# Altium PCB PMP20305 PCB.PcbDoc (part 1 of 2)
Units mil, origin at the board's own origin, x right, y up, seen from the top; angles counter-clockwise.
Board outline 4400 x 7000 mil, 4 copper layers (Top Layer, GND, Signal Layer 2, Bottom Layer), stack 61.2 mil thick; 121 components, 72 nets, 974 pads, 10 vias.
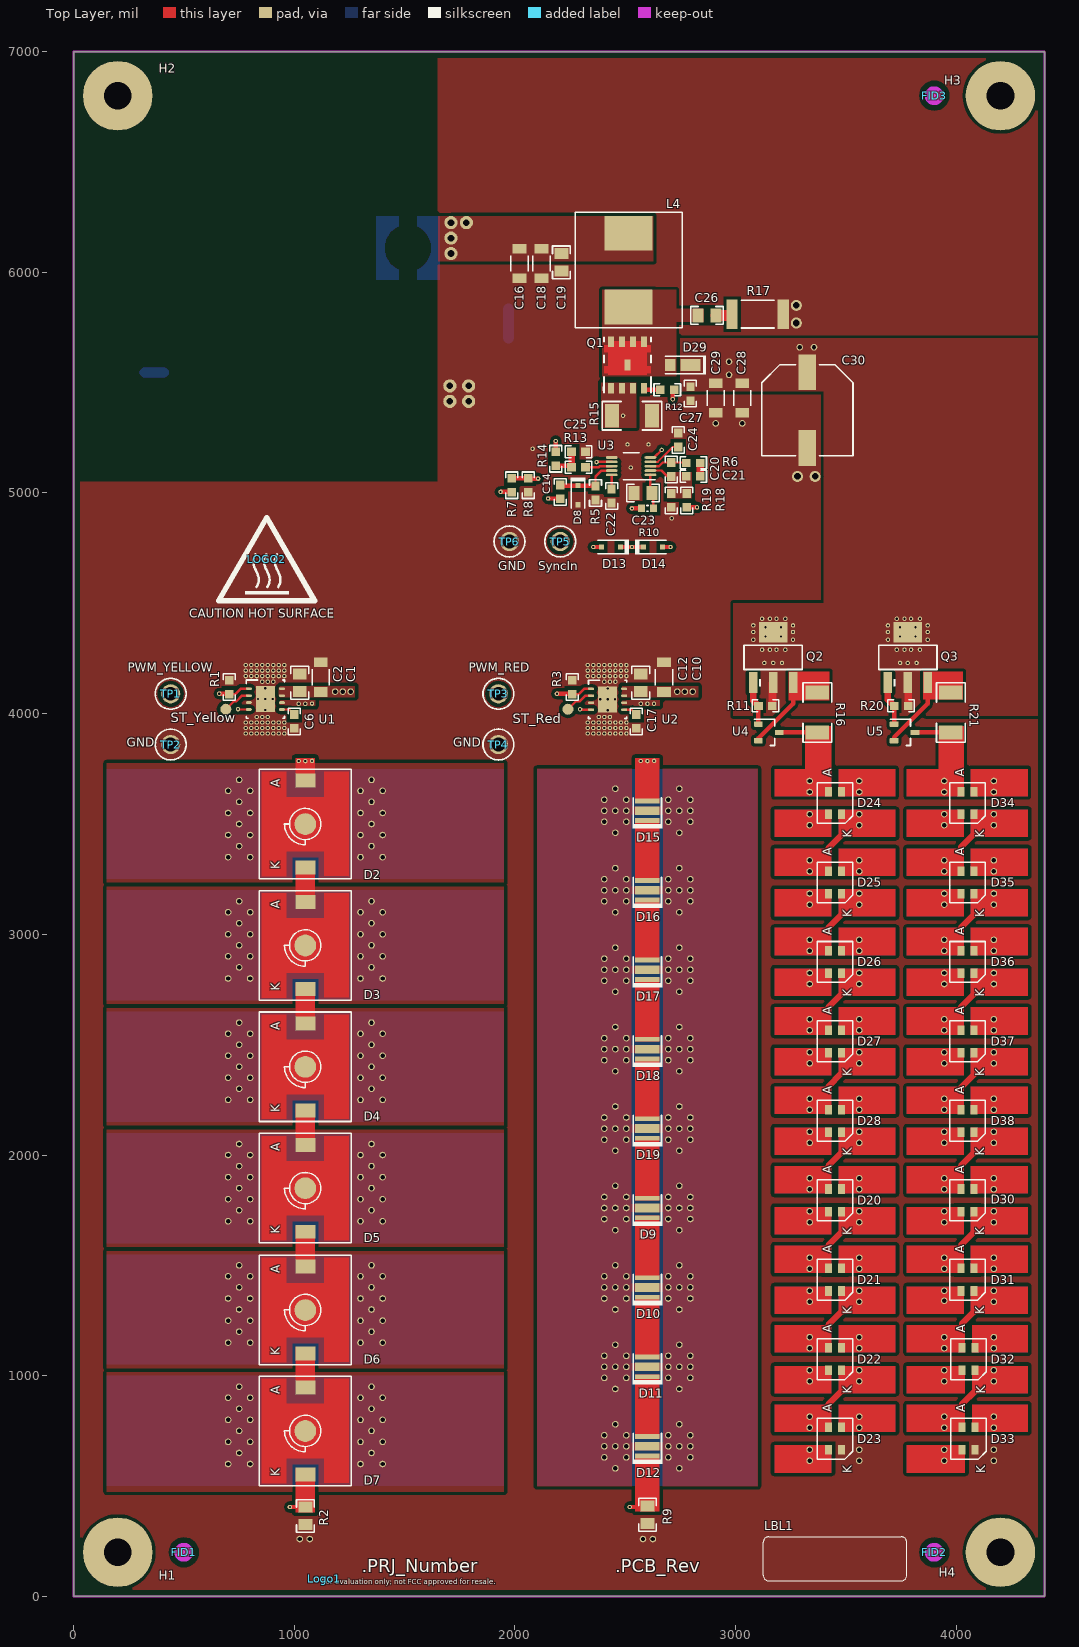
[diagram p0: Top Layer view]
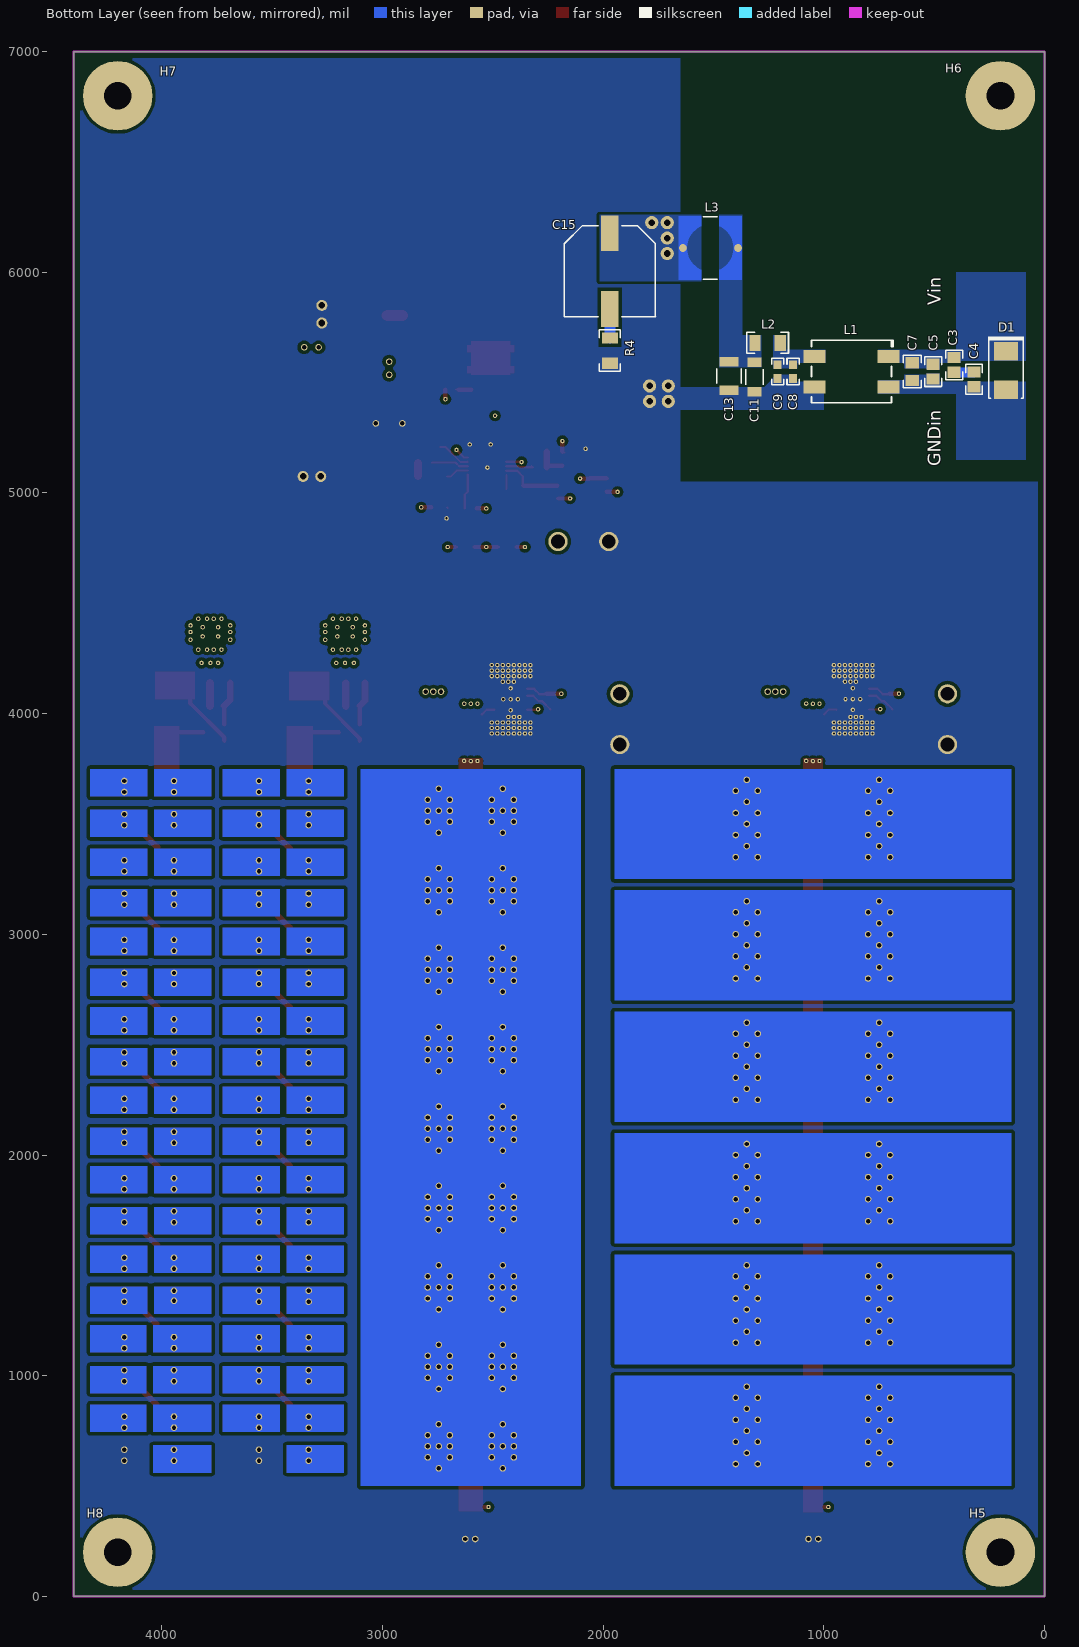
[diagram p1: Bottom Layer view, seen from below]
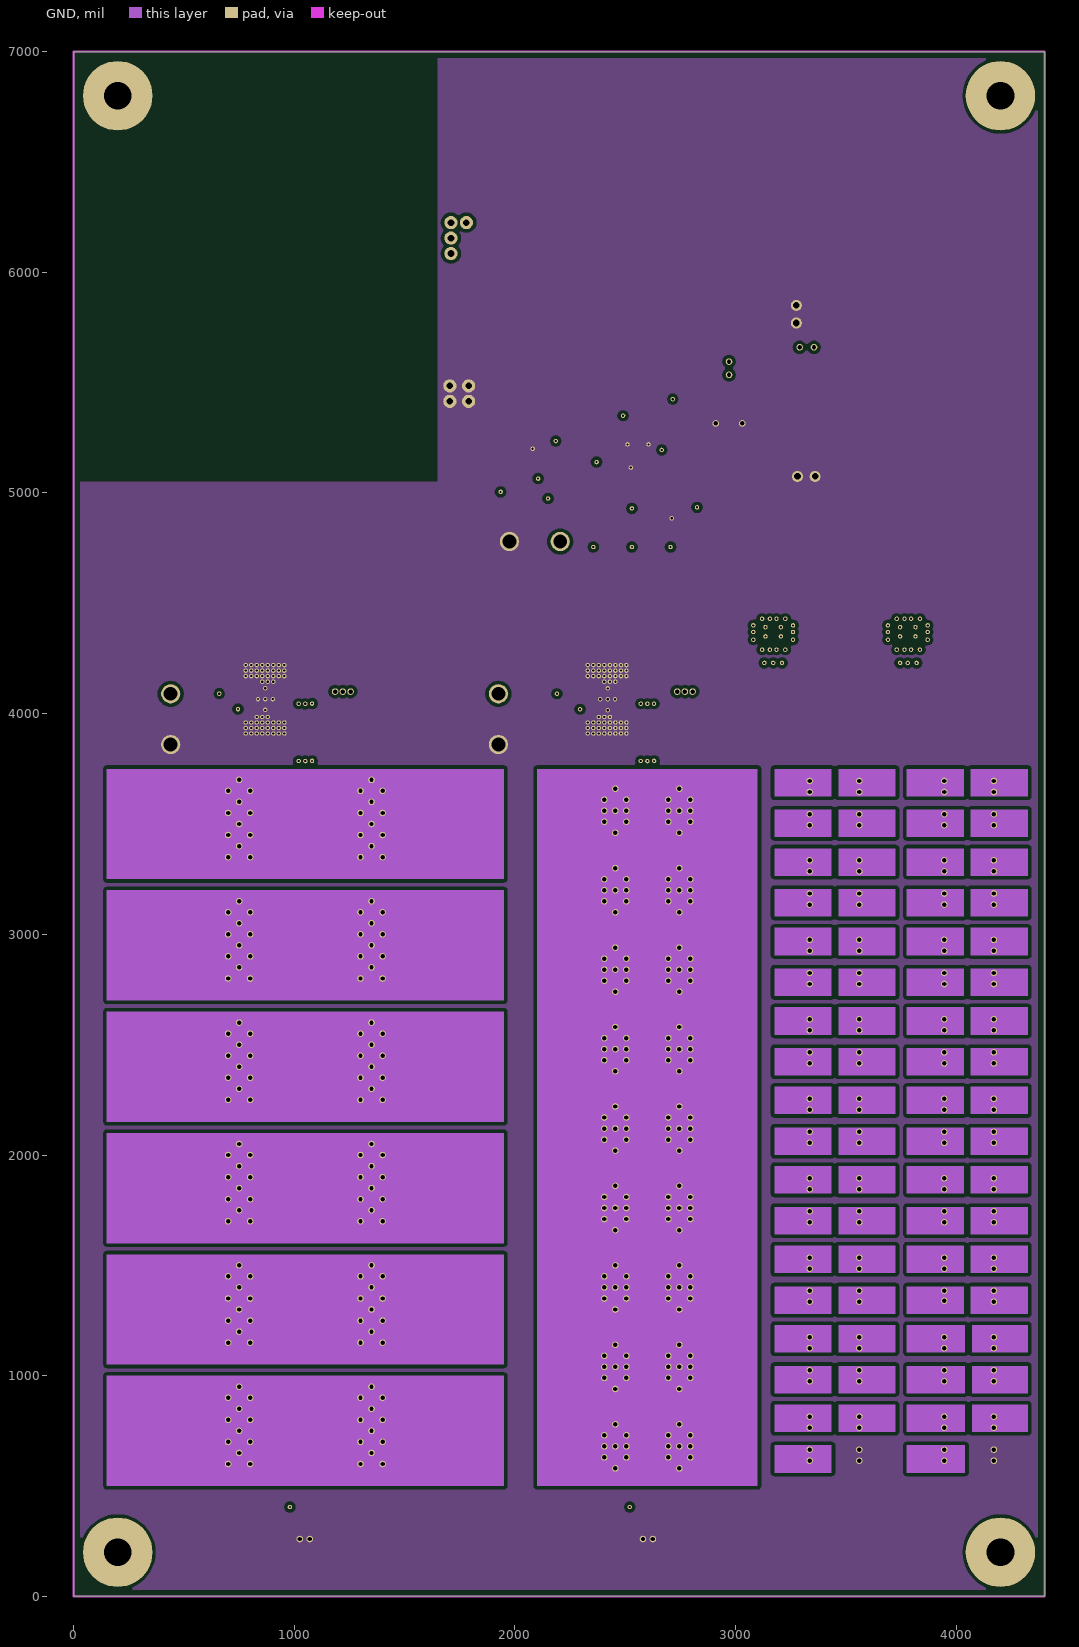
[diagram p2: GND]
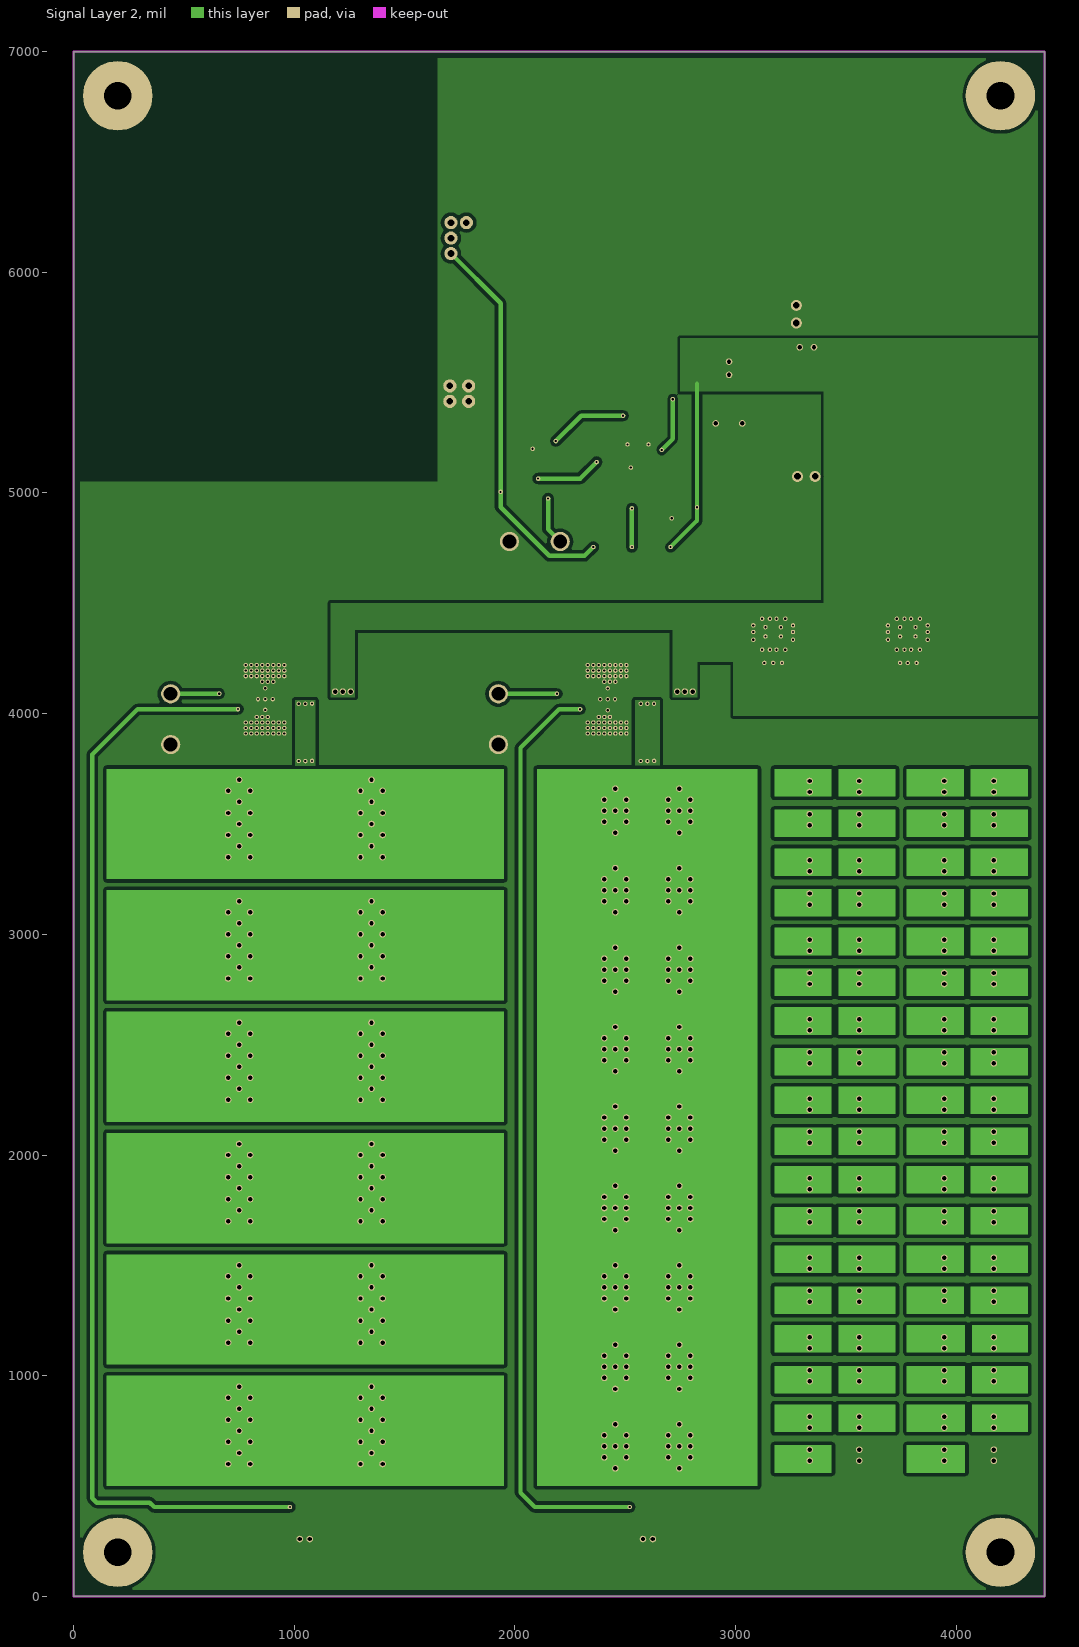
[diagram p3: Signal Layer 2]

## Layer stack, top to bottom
Top Solder: solder mask 0.4, Solder Resist, Dk 3.5
Top Layer: signal copper 2.8
Dielectric1: core 12, FR-4, Dk 4.2
GND: signal copper 2.8
Dielectric 3: prepreg 26, FR-4, Dk 4.2
Signal Layer 2: signal copper 2.8
Dielectric 2: core 12, FR-4, Dk 4.2
Bottom Layer: signal copper 2.8
Bottom Solder: solder mask 0.4, Solder Resist, Dk 3.5

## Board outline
0,0 4400,0 4400,7000 0,7000

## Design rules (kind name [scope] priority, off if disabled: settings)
AcuteAngle [All] p1: minimum=4.50000000000000E+0001 checktracksonly=FALSE
AssemblyTestPointUsage [All] p1: valid=2
Clearance Clearance_Keepouts [((IsTrack Or IsArc) And Not InPoly) And IsFree and IsKeepOut vs ((IsTrack Or IsArc) And Not InPoly) And IsFree and IsKeepOut] p1: gap=0 ignorepadtopadclearanceinfootprint=FALSE
Clearance Clearance_BoardEdge_MountingHoles [OnCopper and InComponentClass('Mounting Holes') vs IsKeepOut] p2: gap=35 ignorepadtopadclearanceinfootprint=FALSE except(0: Arc-Hole Track-Hole SMDPad-Hole THPad-Hole Via-Hole Fill-Hole Poly-Hole Region-Hole Text-Hole)
Clearance Clearance_BoardEdge_Poly [OnCopper and InPoly vs IsKeepOut] p3: gap=25 ignorepadtopadclearanceinfootprint=FALSE except(0: Arc-Hole Track-Hole SMDPad-Hole THPad-Hole Via-Hole Fill-Hole Poly-Hole Region-Hole Text-Hole)
Clearance Clearance_BoardEdge [OnCopper and Not InComponentClass('Logo') and not InComponentClass('FiducialMark') and not InRegion(1000,500,4000,800) and Not IsKeepout vs IsKeepOut] p4: gap=45 ignorepadtopadclearanceinfootprint=FALSE except(0: Arc-Hole Track-Hole SMDPad-Hole THPad-Hole Via-Hole Fill-Hole Poly-Hole Region-Hole Text-Hole)
Clearance Clearance_Poly [InPolygon] p5: gap=15 ignorepadtopadclearanceinfootprint=FALSE except(0: Arc-Hole Track-Hole SMDPad-Hole THPad-Hole Via-Hole Fill-Hole Poly-Hole Region-Hole Text-Hole)
Clearance [All] p6: gap=7.87 ignorepadtopadclearanceinfootprint=FALSE except(0: Arc-Hole Track-Hole SMDPad-Hole THPad-Hole Via-Hole Fill-Hole Poly-Hole Region-Hole Text-Hole)
ComponentClearance ComponentClearance_MountingHoles_FiducialMarks [InComponentClass('Mounting Holes') vs InComponentClass('FiducialMark')] p1: gap=50 collisioncheckmode=3 verticalgap=10 showdistances=FALSE
ComponentClearance ComponentClearance_Shunt [InComponentClass('Header') vs InComponentClass('Shunt')] p2: gap=0 collisioncheckmode=3 verticalgap=0 showdistances=FALSE
ComponentClearance ComponentClearance_Logo [InComponentClass('Logo')] p3: gap=50 collisioncheckmode=3 verticalgap=10 showdistances=FALSE
ComponentClearance ComponentClearance_ScrewToNut [(HasFootprint('NY PMS 440 0025 PH')) vs (HasFootprint('Keystone_1902C'))] p4: gap=5 collisioncheckmode=3 verticalgap=10 showdistances=FALSE
ComponentClearance ComponentClearance_MountingHoles [InComponentClass('Mounting Holes')] p5: gap=150 collisioncheckmode=3 verticalgap=100000 showdistances=FALSE
ComponentClearance ComponentClearance_SmallPassives [HasFootprint('0201*') or HasFootprint('0402*') or HasFootprint('0508') or HasFootprint('0603*') or HasFootprint('0612') or HasFootprint('0805*') or HasFootprint('0815*') or HasFootprint('0830*') or HasFootprint('1206*') or HasFootprint('1210*') or HasFootprint('1808*') or HasFootprint('1812*') or HasFootprint('1825*') or HasFootprint('2010*') or HasFootprint('2220*') or HasFootprint('2225*') or HasFootprint('2512*') or HasFootprint('2728*') or HasFootprint('3518*') vs HasFootprint('0201*') or HasFootprint('0402*') or HasFootprint('0508') or HasFootprint('0603*') or HasFootprint('0612') or HasFootprint('0805*') or HasFootprint('0815*') or HasFootprint('0830*') or HasFootprint('1206*') or HasFootprint('1210*') or HasFootprint('1808*') or HasFootprint('1812*') or HasFootprint('1825*') or HasFootprint('2010*') or HasFootprint('2220*') or HasFootprint('2225*') or HasFootprint('2512*') or HasFootprint('2728*') or HasFootprint('3518*')] p6: gap=20 collisioncheckmode=3 verticalgap=10 showdistances=FALSE
ComponentClearance ComponentClearance_THtoSMT [IsThruComponent vs IsSMTComponent] p7: gap=50 collisioncheckmode=3 verticalgap=30 showdistances=FALSE
ComponentClearance ComponentClearance_THtoTH [IsThruComponent vs IsThruComponent] p8: gap=100 collisioncheckmode=3 verticalgap=30 showdistances=FALSE
ComponentClearance [All] p9: gap=30 collisioncheckmode=3 verticalgap=10 showdistances=FALSE
DiffPairsRouting [All] p1: maxlimit=100 minlimit=10 mostfreqgap=10 toplayer_minwidth=15 toplayer_maxwidth=15 toplayer_prefwidth=15 midlayer1_minwidth=15 midlayer1_maxwidth=15 midlayer1_prefwidth=15 midlayer2_minwidth=15 midlayer2_maxwidth=15 midlayer2_prefwidth=15 bottomlayer_minwidth=15 bottomlayer_maxwidth=15 bottomlayer_prefwidth=15 maxuncoupledlength=1000
FabricationTestPointUsage TestPointUsage [All] p1: valid=2 allowmultiple=FALSE
FabricationTestpoint Testpoint [All] p1: side=3 testpointundercomponent=TRUE minsize=40 maxsize=100 preferedsize=60 minholesize=0 maxholesize=40 preferedholesize=32 testpointgrid=1 allowsidetop=TRUE allowsidebottom=TRUE usegrid=TRUE gridtolerance=0.01
FanoutControl Fanout_LCC [IsLCC] p1: bgadir=Out bgaviamode=Centered fanoutstyle=Auto fanoutdirection=Alternating viagrid=1 // Fanout_LCC (Default Rule)
FanoutControl Fanout_BGA [IsBGA] p2: bgadir=Out bgaviamode=Centered fanoutstyle=Auto fanoutdirection=Alternating viagrid=1 // Fanout_BGA (Default Rule)
FanoutControl Fanout_Default [All] p4: bgadir=Out bgaviamode=Centered fanoutstyle=Auto fanoutdirection=Alternating viagrid=1 // Fanout_Default (Default Rule)
FanoutControl Fanout_Small [(CompPinCount < 5)] p5: bgadir=Out bgaviamode=Centered fanoutstyle=Auto fanoutdirection=OutThenIn viagrid=1 // Fanout_Small (Default Rule)
HoleSize [All] p1: absolutevalues=TRUE maxlimit=251 minlimit=8 maxpercent=80.000 minpercent=20.000
MinimumAnnularRing MinimumAnnularRing_ThermalPadVias [IsVia and InAnyComponent] p1: minimumring=5
MinimumAnnularRing [All] p2: minimumring=5
MinimumSolderMaskSliver MinimumSolderMaskSliver_Logo [InComponentClass('Logo') vs InComponentClass('Logo')] p1: minsoldermaskwidth=0.7
MinimumSolderMaskSliver [All] p2: minsoldermaskwidth=3.94
PlaneConnect [All] p1: planeconnectstyle=Direct reliefexpansion=10 reliefentries=4 reliefconductorwidth=10 reliefairgap=10
PolygonConnect [All] p1: connectstyle=Direct reliefconductorwidth=10 reliefentries=4 polygonreliefangle="90 Angle" airgapwidth=10
RoutingVias ThermalPadVias [IsVia and InAnyComponent] p1: holewidth=7.87 width=19.68 viastyle="Through Hole" minholewidth=7.87 minwidth=19.68 maxholewidth=12.99 maxwidth=23.62
RoutingVias [All] p2: holewidth=16 width=34 viastyle="Through Hole" minholewidth=7.87 minwidth=26 maxholewidth=40 maxwidth=65
SilkToBoardRegionClearance [Not ((IsComment or IsDesignator) And (Hide <> 'False')) and not InRegion(1000,500,4000,800)] p1:
SilkToSilkClearance SilkToSilkClearance_Pb-FreeLogo [(HasFootprint('Pb-Free_Overlay_Medium') OR HasFootprint('Pb-Free_Overlay_Small')) vs (HasFootprint('Pb-Free_Overlay_Medium') OR HasFootprint('Pb-Free_Overlay_Small'))] p1: silktosilkclearance=0
SilkToSilkClearance [All] p2: silktosilkclearance=4
SilkToSolderMaskClearance SilkToComonentPadClearance [IsPad and InAnycomponent] p1: minsilkscreentomaskgap=5 clearancetoexposedcopper=TRUE
SilkToSolderMaskClearance "Silk to Solder Mask Opening" [All] p2: minsilkscreentomaskgap=4 clearancetoexposedcopper=FALSE
SolderMaskExpansion [All] p1: expansion=1.97
Width [All] p1: maxlimit=100 minlimit=6 preferedwidth=10 checkconnectedcopper=TRUE
15 further rules are at their usual default settings.

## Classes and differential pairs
component class FiducialMark: FID1 FID2 FID3
component class PMP20305_EVM_Hardware: FID1 FID2 FID3 H1 H2 H3 H4 H5 H6 H7 H8 LBL1 Logo1 LOGO2
component class "PMP20305 Schematic": C1 C2 C3 C4 C5 C6 C7 C8 C9 C10 C11 C12 C13 C14 C15 C16 C17 C18 C19 C20 C21 C22 C23 C24 C25 C26 C27 C28 C29 C30 D1 D2 D3 D4 D5 D6 D7 D8 D9 D10 D11 D12 D13 D14 D15 D16 D17 D18 D19 D20 D21 D22 D23 D24 D25 D26 D27 D28 D29 D30 D31 D32 D33 D34 D35 D36 D37 D38 L1 L2 L3 L4 Q1 Q2 Q3 R1 R2 R3 R4 R5 R6 R7 R8 R9 R10 R11 R12 R13 R14 R15 R16 R17 R18 R19 R20 R21 TP1 TP2 TP3 TP4 TP5 TP6 U1 U2 U3 U4 U5
component class Label: LBL1
component class "Mounting Holes": H1 H2 H3 H4

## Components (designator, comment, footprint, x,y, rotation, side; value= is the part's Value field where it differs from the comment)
C1 "GRM31CR71H475KA12L" 1206_180 1120,4165 r90 top
C2 "08055C104JAT2A" 0805_HV 1025,4140 r90 top
C3 "CGA4J3X7S2A105K125AB" 0805 410,5580 r270 bottom
C4 "CGA4J3X7S2A105K125AB" 0805 320,5515 r270 bottom
C5 "CGA4J3X7S2A105K125AB" 0805 505,5550 r270 bottom
C6 "GRM188R71C473KA01D" 0603 1000,3965 r270 top
C7 "CGA4J2X7R2A104K125AA" 0805_HV 600,5550 r270 bottom
C8 "GRM188R71H104KA93D" 0603 1140,5550 r90 bottom
C9 "UMK107AB7105KA-T" 0603 1210,5550 r270 bottom
C10 "GRM31CR71H475KA12L" 1206_180 2675,4165 r90 top
C11 "GRM31CR71H475KA12L" 1206_180 1315,5525 r270 bottom
C12 "08055C104JAT2A" 0805_HV 2570,4140 r90 top
C13 "C3225X7R1H106M250AC" 1210_280 1430,5530 r270 bottom
C14 "06035A101JAT2A" 0603 2205,5005 r90 top
C15 "EEE-FC1H470P" SM_RADIAL_G 1970,6005 r270 bottom
C16 "GRM31CR71H475KA12L" 1206_180 2020,6040 r270 top
C17 "GRM188R71C473KA01D" 0603 2550,3965 r270 top
C18 "GRM31CR71H475KA12L" 1206_180 2120,6040 r270 top
C19 "C2012X7R1H225K125AC" 0805_HV 2210,6045 r270 top
C20 "GRM188R71C184KA01D" 0603 2707.98,5106.28 r90 top
C21 "GRM1885C1E561JA01D" 0603 2807.98,5076.28 r0 top
C22 "GCM155R71C224KE02" 0603 2437.98,4986.28 r270 top
C23 "08055C104JAT2A" 0805_HV 2580,5000 r180 top
C24 "885012206071" 0603 2740,5240 r270 top
C25 "06035A101JAT2A" 0603 2287.98,5186.28 r0 top
C26 "C0805C331J1GACTU" 0805_HV 2870,5805 r180 top
C27 "CGA3E3X8R1H104K080AB" 0603 2795,5450 r270 top
C28 "C3216X7R1H475M160AC" 1206_190 3030,5430 r270 top
C29 "C3216X7R1H475M160AC" 1206_190 2910,5430 r270 top
C30 "EEE-FC1V221P" SM_RADIAL_G 3325,5375 r270 top
D1 "SMBJ18A-13-F" SMB 175,5555 r270 bottom
D2 "LY-W5SM" LED_goldendragon 1050,3500 r90 top
D3 "LY-W5SM" LED_goldendragon 1050,2950 r90 top
D4 "LY-W5SM" LED_goldendragon 1050,2400 r90 top
D5 "LY-W5SM" LED_goldendragon 1050,1850 r90 top
D6 "LY-W5SM" LED_goldendragon 1050,1298 r90 top
D7 "LY-W5SM" LED_goldendragon 1050,750 r90 top
D8 "BAT42WS-7-F" SOD-323 2285,4990 r270 top
D9 "LH CP7P-2T3T-1" "LH CP7P_RED" 2600,1760 r0 top
D10 "LH CP7P-2T3T-1" "LH CP7P_RED" 2600,1400 r0 top
D11 "LH CP7P-2T3T-1" "LH CP7P_RED" 2600,1040 r0 top
D12 "LH CP7P-2T3T-1" "LH CP7P_RED" 2600,680 r0 top
D13 "BAV116WSQ-7" SOD-323 2435,4755 r180 top
D14 "BAV116WSQ-7" SOD-323 2625,4755 r0 top
D15 "LH CP7P-2T3T-1" "LH CP7P_RED" 2600,3560 r0 top
D16 "LH CP7P-2T3T-1" "LH CP7P_RED" 2600,3200 r0 top
D17 "LH CP7P-2T3T-1" "LH CP7P_RED" 2600,2840 r0 top
D18 "LH CP7P-2T3T-1" "LH CP7P_RED" 2600,2480 r0 top
D19 "LH CP7P-2T3T-1" "LH CP7P_RED" 2600,2120 r0 top
D20 "LR-E6SF" LED_PowerTOPLED_GF 3450,1795 r90 top
D21 "LR-E6SF" LED_PowerTOPLED_GF 3450,1435 r90 top
D22 "LR-E6SF" LED_PowerTOPLED_GF 3450,1075 r90 top
D23 "LR-E6SF" LED_PowerTOPLED_GF 3450,715 r90 top
D24 "LR-E6SF" LED_PowerTOPLED_GF 3450,3595 r90 top
D25 "LR-E6SF" LED_PowerTOPLED_GF 3450,3235 r90 top
D26 "LR-E6SF" LED_PowerTOPLED_GF 3450,2875 r90 top
D27 "LR-E6SF" LED_PowerTOPLED_GF 3450,2515 r90 top
D28 "LR-E6SF" LED_PowerTOPLED_GF 3450,2155 r90 top
D29 "FSV340FP" SOD-123HE 2760,5580 r180 top
D30 "LR-E6SF" LED_PowerTOPLED_GF 4050,1795 r90 top
D31 "LR-E6SF" LED_PowerTOPLED_GF 4050,1435 r90 top
D32 "LR-E6SF" LED_PowerTOPLED_GF 4055,1075 r90 top
D33 "LR-E6SF" LED_PowerTOPLED_GF 4055,715 r90 top
D34 "LR-E6SF" LED_PowerTOPLED_GF 4050,3595 r90 top
D35 "LR-E6SF" LED_PowerTOPLED_GF 4050,3235 r90 top
D36 "LR-E6SF" LED_PowerTOPLED_GF 4050,2875 r90 top
D37 "LR-E6SF" LED_PowerTOPLED_GF 4050,2515 r90 top
D38 "LR-E6SF" LED_PowerTOPLED_GF 4050,2155 r90 top
FID1 "Fiducial" Fiducial10-20 500,200 r0 top
FID2 "Fiducial" Fiducial10-20 3900,200 r0 top
FID3 "Fiducial" Fiducial10-20 3900,6800 r0 top
H1 "NY PMS 440 0025 PH" "NY PMS 440 0025 PH" 200,200 r0 top
H2 "NY PMS 440 0025 PH" "NY PMS 440 0025 PH" 200,6800 r0 top
H3 "NY PMS 440 0025 PH" "NY PMS 440 0025 PH" 4200,6800 r0 top
H4 "NY PMS 440 0025 PH" "NY PMS 440 0025 PH" 4200,200 r0 top
H5 "1902C" Keystone_1902C 200,200 r180 bottom
H6 "1902C" Keystone_1902C 200,6800 r180 bottom
H7 "1902C" Keystone_1902C 4200,6800 r180 bottom
H8 "1902C" Keystone_1902C 4200,200 r180 bottom
L1 "ACM9070-701-2PL-TL01" TDK_ACM9070 875,5550 r270 bottom
L2 "HR2220V801R-10" 1206 1255,5680 r0 bottom
L3 "7440620015" WE-TPC_6823 1515,6110 r270 bottom
L4 "MSS1246T-153MLB" MSS1246T 2515,6010 r270 top
LBL1 "Size: 0.65\" x 0.20 \"" Label_650x200 3450,170 r0 top
Logo1 "FCC disclaimer" FCC_disclaimer 1135,80 r90 top
LOGO2 "CAUTION HOT SURFACE" IEC_HotSurface_Medium 875,4700 r0 top
Q1 "STL7N6LF3" PowerFLAT5x6_R 2510,5580 r90 top
Q2 "PZT2222A" SOT-223 3170,4255 r90 top
Q3 "PZT2222A" SOT-223 3780,4255 r90 top
R1 "CRCW060310K0JNEA" 0603 705,4120 r270 top
R2 "CRCW08051R18FKEA" 0805_HV 1050,365 r90 top
R3 "CRCW060310K0JNEA" 0603 2260,4120 r270 top
R4 "CRCW12061R00JNEA" 1206 1970,5645 r90 bottom
R5 "RT0603DRE077K23L" 0603 2365,5000 r90 top
R6 "RC0603FR-073KL" 0603 2807.98,5136.28 r0 top
R7 "CRCW060334K8FKEA" 0603 1985,5035 r270 top
R8 "CRCW06038K25FKEA" 0603 2060,5035 r90 top
R9 "CRCW08051R18FKEA" 0805_HV 2600,370 r90 top
R10 "CRCW060310R0JNEA" 0603L 2600,4930 r180 top
R11 "RC0603JR-073K3L" 0603 3135,4035 r0 top
R12 "CRCW06030000Z0EA" 0603 2690,5468.19 r180 top
R13 "RT0603BRD075K56L" 0603 2287.98,5116.28 r0 top
R14 "CRCW0603100RJNEA" 0603 2185,5155 r90 top
R15 "CSRN2010FK75L0" 2010 2530,5350 r180 top
R16 "CRCW201049R9FKEF" 2010 3370,4005 r90 top
R17 "CRCW25128R20JNEG" 2512 3100,5810 r0 top
R18 "RC0603FR-0720KL" 0603 2777.98,4966.28 r270 top
R19 "RT0603DRE07976RL" 0603 2707.98,4966.28 r90 top
R20 "RC0603JR-073K3L" 0603 3750,4035 r0 top
R21 "CRCW201049R9FKEF" 2010 3975,4005 r90 top
TP1 "PWM_YELLOW" Keystone5012 440,4090 r0 top
TP2 "GND" Keystone5011 440,3860 r0 top
TP3 "PWM_RED" Keystone5012 1925,4090 r0 top
TP4 "GND" Keystone5011 1925,3860 r0 top
TP5 "SyncIn" Keystone5012 2205,4780 r0 top
TP6 "GND" Keystone5011 1975,4780 r0 top
U1 "TL4242TDRJRQ1" DRJ0008A#1 868.94,4116.06 r0 top
U2 "TL4242TDRJRQ1" DRJ0008A#2 2420,4065 r0 top
U3 "LM5022QDGSRQ1" DGS0010A_N 2526.3,5121.28 r180 top
U4 "TL431AQDBZRQ1" DBZ0003A_N 3150,3915 r0 top
U5 "TL431AQDBZRQ1" DBZ0003A_N 3765,3915 r0 top

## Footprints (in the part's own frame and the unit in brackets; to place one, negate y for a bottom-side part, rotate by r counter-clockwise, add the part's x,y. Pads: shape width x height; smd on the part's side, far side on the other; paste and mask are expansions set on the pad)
0603 [mm] "0603 from SM-752 data"
  rect 1x0.95 smd: 1(-0.8,0) 2(0.8,0)
  silkscreen extent -1.52,-0.69 1.52,0.69, body extent -0.87,-0.47 0.87,0.47, height 1
0603L [mm] "0603 from SM-752 data"
  rect 0.8x0.85 smd: 1(-0.7,0) 2(0.7,0)
  silkscreen extent -0.07,-0.33 0.07,0.33, body extent -0.87,-0.47 0.87,0.47, height 1
0805 [mm] "0805 from SM-752 data"
  rect 1.3x1.5 smd: 1(-0.85,0) 2(0.85,0)
  silkscreen extent -1.72,-0.97 1.72,0.97, body extent -1.1,-0.72 1.1,0.72, height 1.45
0805_HV [mil] "0805 with 30mil clearance between pads"
  rect 50x63 smd: 1(-40,0) 2(40,0)
  silkscreen extent -74,-40 74,40, body extent -43,-29 43,29, height 57
1206 [mm] "1206 from SM-752 data"
  rect 1.3x1.85 smd: 1(-1.45,0) 2(1.45,0)
  silkscreen extent -2.4,-1.21 2.4,1.21, body extent -1.7,-0.9 1.7,0.9, height 1.35
1206_180 [mm] "1206_180"
  rect 1.1x1.6 smd: 1(-1.7,0) 2(1.7,0)
  silkscreen extent -0.9,-1 0.9,1, body extent -1.75,-0.95 1.75,0.95, height 1.8
1206_190 [mm] "1206_190"
  rect 1.1x1.6 smd: 1(-1.7,0) 2(1.7,0)
  silkscreen extent -0.9,-1 0.9,1, body extent -1.75,-0.95 1.75,0.95, height 1.9
1210_280 [mm] "SMD, 2-Leads, Body 3.6x2.8mm, Height 2.8mm"
  rect 1.1x2.2 smd: 1(-1.65,0) 2(1.65,0)
  silkscreen extent -0.84,-1.4 0.84,1.4, body extent -1.8,-1.4 1.8,1.4, height 2.8
2010 [mm] "Chip Capacitor, Body 5.08x2.54mm, IPC Medium Density"
  rect 1.6x2.7 smd: 1(-2.3,0) 2(2.3,0)
  silkscreen extent -3.42,-1.65 3.42,1.65, body extent -2.73,-1.45 2.73,1.45, height 1.66
2512 [mm] "Chip Resistor, Body 6.3x3.2mm, IPC Medium Density"
  rect 1.3x3.4 smd: 1(-2.95,0) 2(2.95,0)
  silkscreen extent -1.9,-1.6 1.9,1.6, body extent -3.22,-1.67 3.22,1.67, height 0.71
DBZ0003A_N [mm] "SOT23, 3-Leads, Body 2.9x1.3mm, Pitch 0.95mm, Lead Span 2.4mm, IPC Medium Density"
  rrect17% 1x0.6 smd: 1(-1.2,0.95) 2(-1.2,-0.95) 3(1.2,0)
  silkscreen extent -1.65,-1.5 0.7,1.5, body extent -1.26,-1.46 1.26,1.46, height 0.98
DGS0010A_N [mm] "TSSOP, 10-Leads, Body 3x3mm, Pitch 0.5mm, IPC Medium Density"
  oval 1.35x0.3 smd: 1(-2.225,1) 2(-2.225,0.5) 3(-2.225,0) 4(-2.225,-0.5) 5(-2.225,-1) 6(2.225,-1) 7(2.225,-0.5) 8(2.225,0) 9(2.225,0.5) 10(2.225,1)
  silkscreen extent -2.75,-1.55 0.9,1.55, body extent -2.45,-1.5 2.45,1.5, height 0.96
DRJ0008A#1 [mm] "SON, 8-Leads, Body 4x4mm, Pitch 0.8mm, Thermal Pad 3x2.2mm, TI Recommended"
  oval 0.7x0.3 smd: 1(-1.9,-0.07) 2(-1.9,-0.87) 3(-1.9,-1.67) 4(-1.9,-2.47) 5(1.9,-2.47) 6(1.9,-1.67) 7(1.9,-0.87) 8(1.9,-0.07)
  rect 2.2x3 smd paste-1.1: 9(0,-1.27)
  silkscreen extent -2.2,-3.47 2.2,0.93, body extent -2.05,-3.32 2.05,0.78, height 0.81
DRJ0008A#2 [mm] "SON, 8-Leads, Body 4x4mm, Pitch 0.8mm, Thermal Pad 3x2.2mm, TI Recommended"
  oval 0.7x0.3 smd: 1(-1.9,1.2) 2(-1.9,0.4) 3(-1.9,-0.4) 4(-1.9,-1.2) 5(1.9,-1.2) 6(1.9,-0.4) 7(1.9,0.4) 8(1.9,1.2)
  rect 2.2x3 smd paste-1.1: 9(0,0)
  silkscreen extent -2.2,-2.2 2.2,2.2, body extent -2.05,-2.05 2.05,2.05, height 0.81
FCC_disclaimer [mil]
Fiducial10-20 [mm]
  round 1 smd mask+0.5: 1(0,0)
  Top Layer keep-out circle w1.178: c0,0 r0.5
IEC_HotSurface_Medium [mil]
  silkscreen extent -217,-188 217,188
Keystone5011 [mil] "Keystone Multipurpose loops"
  round 87 hole 63: 1(0,0)
  silkscreen extent -70,-70 70,70, body extent -63,-63 63,62, height 319
Keystone5012 [mil] "Keystone Multipurpose loops"
  round 87 hole 63: 1(0,0)
  silkscreen extent -70,-70 70,70, body extent -63,-63 63,62, height 319
Keystone_1902C [mil] "Hex Standoff, 4-40 threaded, nylon"
  round 1 on Mech4: 0(0,0)
  body extent -145,-126 146,126, height 501
Label_650x200 [mil] "Thermal Transfer Label"
  round 1 on Mech13: 0(0,0)
  silkscreen extent -325,-100 325,100, body extent -325,-100 325,100, height 1
LED_goldendragon [mm] "Per LA_LR_LY_W5SM_Pb_free.pdf, page 11 dated 2008-09-04"
  round 2.5 smd mask+0.75: 1(-0.013,0.003)
  rect 1.6x2.3 smd mask+1: 1(4.985,0) 2(-5.015,0)
  Top Layer region: 3.125,3.048 -3.175,3.048 -3.175,-3.048 3.125,-3.048
  Top Layer region: -5.987,-5.003 6.013,-5.003 6,-2.175 0.025,-2.175 -5.975,-2.175
  Top Layer region: 6,5 -6,5 -6,2.2 0,2.2 6,2.2
  silkscreen extent -6.3,-5.3 6.3,5.3, body extent -3.61,-3.09 3.59,3.11, height 2
LED_PowerTOPLED_GF [mm] "Osram recommended land pattern,  \"LA_LO_LR_LS_LY_E6SF_Pb_free.pdf\", dated 2008-11-27"
  rect 1.1x0.8 smd: 1(-1.3,0.75) 2(-1.3,-0.75) 3(1.3,-0.75) 4(1.3,0.75)
  silkscreen extent -2.35,-2.05 2.35,2.05, body extent -1.7,-1.5 1.7,1.5, height 2.1
"LH CP7P_RED" [mm] "OSRAM"
  rect 2.8x0.55 smd paste-0.3: 1(0,1.125) 2(0,-1.125)
  rect 2.8x1 smd paste-0.5: 3(0,0)
  silkscreen extent -1.72,-2.05 1.73,1.5, body extent -1.55,-1.55 1.55,1.55, height 2.35
MSS1246T [mm] "Recommended land pattern for Coilcraft MSS1246T series Document 540-2 rev 10/15/08"
  rect 4x5.5 smd: 1(-4.25,0) 2(4.25,0)
  silkscreen extent -6.64,-6.14 6.63,6.16, body extent -6.15,-6.15 6.15,6.15, height 4.8
"NY PMS 440 0025 PH" [mm] "4-40 nylon screw and mounting hole"
  round 8 hole 3.2: 1(0,0)
  body extent -3.3,-3.3 3.3,3.3, height 2.69
PowerFLAT5x6_R [mm] "SMD, 8-Leads, Body 6.15x5.2mm, Pitch 1.27mm"
  rect 1.25x0.65 smd: 1(-2.675,1.905) 2(-2.675,0.635) 3(-2.675,-0.635) 4(-2.675,-1.905) 5(2.675,-1.905) 6(2.675,-0.635) 7(2.675,0.635) 8(2.675,1.905) 9(0,0)
  Top Layer region: -0.96,2.7 -0.96,2.225 -1.15,2.225 -1.15,-2.225 -0.96,-2.225 -0.96,-2.7 -0.16,-2.7 -0.16,-2.225 1.49,-2.225 1.49,-2.7 2.29,-2.7 2.29,-2.225 2.75,-2.225 2.75,2.225 2.29,2.225 2.29,2.7 1.49,2.7 1.49,2.225 -0.16,2.225 -0.16,2.7
  silkscreen extent -3.17,-2.7 3.17,2.9, body extent -3.17,-2.7 3.17,2.7, height 1.01
SM_RADIAL_G [mm] "10 x 10.2mm:  Panasonic G"
  rect 4.1x2 smd: 1(-4.35,0) 2(4.35,0)
  silkscreen extent -5.25,-5.25 5.25,5.25, body extent -5.25,-5.25 5.25,5.25, height 10.5
SMB [mil] "Molded Diode, 2-Leads, Body 5.4x3.6mm, IPC Medium Density, based on OnSemi component dimensions"
  rect 85x107.99 smd: 1(-87.01,0) 2(87.01,0)
  silkscreen extent -155,-82 125,82, body extent -106,-71 106,71, height 91
SOD-123HE [mm] "SMD, 2-Leads, Body 2.8x1.8mm"
  rect 2.3x1.4 smd: 1(-0.9,0)
  rect 1.25x1.4 smd: 2(1.425,0)
  silkscreen extent -2.7,-1.1 2,1.1, body extent -1.5,-0.97 1.5,0.97, height 1
SOD-323 [mm] "NXP recommended land pattern"
  rect 0.6x0.6 smd paste-0.05: 1(-1.1,0) 2(1.1,0)
  silkscreen extent -2.06,-0.86 1.53,0.86, body extent -1.3,-0.67 1.3,0.68, height 1.1
SOT-223 [mm] "SOT223/SC73, 4-Leads, Body 6.5x3.5mm, Pitch 2.3mm, Lead Span 7mm, IPC Medium Density"
  rrect10% 2.4x1 smd: 1(-2.9,2.3) 2(-2.9,0) 3(-2.9,-2.3)
  rrect4% 2.4x3.3 smd: 4(2.9,0)
  silkscreen extent -3.32,-3.35 1.4,3.35, body extent -3.5,-3.25 3.5,3.25, height 1.62
TDK_ACM9070 [mm] "SMD, 4-Leads, Body 9x7mm"
  rect 1.5x2.5 smd: 1(-1.75,4.25) 2(1.75,4.25) 3(1.75,-4.25) 4(-1.75,-4.25)
  silkscreen extent -3.6,-4.6 3.6,4.77, body extent -3.6,-4.6 3.6,4.6, height 4.5
WE-TPC_6823 [mm] "Wurth"
  round 0.9 smd: 1(0,3.2) 2(0,-3.15)
  Top Layer region: 3.65,-1.05 2.5,-1.05 2.485,-1.055 1.743,-2.062 0.626,-2.626 -0.626,-2.626 -1.743,-2.062 -2.485,-1.055 -2.485,-1.055 -2.5,-1.05 -3.65,-1.05 -3.65,-3.65 3.65,-3.65
  Top Layer region: -3.65,1.05 -2.5,1.05 -2.485,1.055 -1.743,2.062 -0.626,2.626 0.626,2.626 1.743,2.062 2.485,1.055 2.485,1.055 2.5,1.05 3.65,1.05 3.65,3.65 -3.65,3.65
  silkscreen extent -3.6,-0.8 3.6,0.8, body extent -3.5,-3.5 3.5,3.5, height 2.5

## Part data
C1 C10 C11 C16 C18: "CAP, CERM, 4.7 µF, 50 V, +/- 10%, X7R, 1206"
C2 C12 C23: "CAP, CERM, 0.1 µF, 50 V, +/- 5%, X7R, 0805"
C3 C4 C5: library part Capacitor, "CAP, CERM, 1uF, 100V, X7S, 10%, 0805"
C6 C17: "CAP, CERM, 0.047 µF, 16 V, +/- 10%, X7R, 0603"
C7: "CAP, CERM, 0.1 µF, 100 V, +/- 10%, X7R, AEC-Q200 Grade 1, 0805"
C8: "CAP, CERM, 0.1 µF, 50 V, +/- 10%, X7R, 0603"
C9: "CAP, CERM, 1 µF, 50 V, +/- 10%, X7R, 0603"
C13: "CAP, CERM, 10 µF, 50 V, +/- 20%, X7R, 1210"
C14 C25: "CAP, CERM, 100 pF, 50 V, +/- 5%, C0G/NP0, 0603"
C15: "CAP, AL, 47 µF, 50 V, +/- 20%, 0.3 ohm, SMD"
C19: "CAP, CERM, 2.2 µF, 50 V, +/- 10%, X7R, 0805"
C20: "CAP, CERM, 0.18 µF, 16 V, +/- 10%, X7R, 0603"
C21: "CAP, CERM, 560 pF, 25 V, +/- 5%, C0G/NP0, 0603"
C22: "CAP, CERM, 0.22 µF, 16 V, +/- 10%, X7R, AEC-Q200 Grade 1, 0603"
C24: "CAP, CERM, 0.1 µF, 25 V, +/- 10%, X7R, 0603"
C26: "CAP, CERM, 330 pF, 100 V, +/- 5%, C0G/NP0, 0805"
C27: "CAP, CERM, 0.1 µF, 50 V, +/- 10%, X8R, AEC-Q200 Grade 0, 0603"
C28 C29: "CAP, CERM, 4.7 µF, 50 V, +/- 20%, X7R, 1206_190"
C30: "CAP, AL, 220 µF, 35 V, +/- 20%, 0.15 ohm, SMD"
D1: "Diode, TVS, Uni, 18 V, 600 W, SMB"
D2 D3 D4 D5 D6 D7: "LED, Yellow, SMD"
D8: "Diode, Schottky, 30 V, 0.2 A, SOD-323"
D9 D10 D11 D12 D15 D16 D17 D18 D19 D20 D21 D22 D23 D24 D25 D26 D27 D28 D30 D31 D32 D33 D34 D35 D36 D37 D38: "LED, Red, SMD"
D13 D14: library part Diode, "Diode, Standard, 85V, 215mA, SOD-323, AEC-Q101"
D29: "Diode, Schottky, 40 V, 3 A, AEC-Q101, SOD-123HE"
FID1 FID2 FID3: "Fiducial mark.  There is nothing to buy or mount."
H1 H2 H3 H4: "Machine Screw, Round, #4-40 x 1/4, Nylon, Philips panhead"
H5 H6 H7 H8: "Standoff, Hex, 0.5\"L #4-40 Nylon"
L1: "Coupled inductor, 5 A, 0.01 ohm, SMD"
L2: "Ferrite Bead, 800 ohm @ 100 MHz, 8 A, 1206"
L3: "Inductor, Shielded Drum Core, Metal Composite, 1.5 µH, 4 A, 0.01 ohm, SMD"
L4: "Inductor, Shielded Drum Core, Ferrite, 15 µH, 3.4 A, 0.05 ohm, SMD"
LBL1: library part THT-14-423-10, "Thermal Transfer Printable Labels, 0.650\" W x 0.200\" H - 10,000 per roll"
Logo1: library part FCC_disclaimer, "FCC_disclaimer"
LOGO2: library part IEC_HotSurface, "IEC 61010-1 Hot Surface Warning"
Q1: "MOSFET, N-CH, 60 V, 20 A, AEC-Q101, 8-PowerVDFN"
Q2 Q3: library part "PZT2222A, Fairchild Semiconductor", "Transistor, NPN, 40 V, 1 A, SOT-223"
R1 R3: "RES, 10 k, 5%, 0.1 W, 0603"
R2 R9: "RES, 1.18, 1%, 0.125 W, 0805"
R4: "RES, 1.0 ohm, 5%, 0.25W, 1206"
R5: "RES, 7.23 k, 0.5%, 0.1 W, 0603"
R6: "RES, 3.00 k, 1%, 0.1 W, 0603"
R7: "RES, 34.8 k, 1%, 0.1 W, 0603"
R8: "RES, 8.25 k, 1%, 0.1 W, 0603"
R10: "RES, 10, 5%, 0.1 W, 0603"
R11 R20: "RES, 3.3 k, 5%, 0.1 W, 0603"
R12: "RES, 0, 5%, 0.1 W, 0603"
R13: "RES, 5.56 k, 0.1%, 0.1 W, 0603"
R14: "RES, 100, 5%, 0.1 W, 0603"
R15: "RES, 0.075, 1%, 1 W, 2010"
R16 R21: "RES, 49.9, 1%, 0.75 W, AEC-Q200 Grade 0, 2010"
R17: "RES, 8.2, 5%, 1 W, AEC-Q200 Grade 0, 2512"
R18: "RES, 20.0 k, 1%, 0.1 W, 0603"
R19: "RES, 976, 0.5%, 0.1 W, 0603"
TP1 TP3 TP5: library part 5012, "Test Point, Multipurpose, White, TH"
TP2 TP4 TP6: library part 5011, "Test Point, Multipurpose, Black, TH"
U1 U2: "ADJUSTABLE LED DRIVER, DRJ0008A"
U3: "60V Low Side Controller for Boost and SEPIC, DGS0010A"
U4 U5: "Automotive Catalog Adjustable Precision Shunt Regulator, 34 ppm / degC, 100 mA, -40 to 125 degC, 3-pin SOT-23 (DBZ), Green (RoHS & no Sb/Br)"

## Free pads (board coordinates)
  round 50 smd: 0(690,4020) 0(2240,4020)
  round 20 hole 10: 1(660,4090.49) 1(745,4020.49) 1(980,405) 1(1020,3785.49) 1(1020,4045) 1(1050,3785) 1(1050,4044.51) 1(1080.49,3785.98) 1(1080.49,4045.49) 1(2190,4090) 1(2295,4020) 1(2520,405) 1(2570,3785.49) 1(2570,4045) 1(2600,3785) 1(2600,4045) 1(2630,4045) 1(2630.49,3785.98) 6(1935,5005) 6(2080,5200) 6(2105,5065) 6(2150,4975) 6(2185,5235) 6(2355,4755) 6(2370,5140) 6(2490,5350) 6(2510,5220) 6(2525,5115) 6(2530,4755) 6(2530,4930) 6(2605,5220) 6(2665,5195) 6(2705,4755) 6(2710,4885) 6(2715,5425) 6(2825,4935) 180(3135,4391.81) 180(3745,4391.81) 181(3205,4391.81) 181(3815,4391.81) 182(3135,4350) 182(3745,4350) 183(3205,4350) 183(3815,4350) 188(3745,4230) 189(3820,4230) 190(3780,4230) 191(3170,4230) 192(3210,4230) 193(3130,4230) 194(3080,4335) 194(3080,4370) 194(3080,4400) 194(3120,4289.88) 194(3120,4430) 194(3155,4290) 194(3155,4430) 194(3185,4289.88) 194(3185,4430) 194(3225,4289.88) 194(3225,4430) 194(3260,4335) 194(3260,4400) 194(3690,4335) 194(3690,4370) 194(3690,4400) 194(3730,4289.88) 194(3730,4430) 194(3765,4290) 194(3765,4430) 194(3795,4289.88) 194(3795,4430) 194(3835,4289.88) 194(3835,4430) 194(3870,4335) 194(3870,4400) 195(3260,4370) 195(3870,4370) 226(830,4170) 226(905,3960) 226(2380,4170) 226(2455,3960) 227(855,4170) 227(880,3960) 227(2405,4170) 227(2430,3960) 228(855,3960) 228(880,4170) 228(2405,3960) 228(2430,4170) 229(830,3960) 229(905,4170) 229(2380,3960) 229(2455,4170) 230(830,3985) 230(905,4145) 230(2380,3985) 230(2455,4145) 231(855,3985) 231(880,4145) 231(2405,3985) 231(2430,4145) 232(855,4145) 232(880,3985) 232(2405,4145) 232(2430,3985) 233(805,4170) 233(930,3960) 233(2355,4170) 233(2480,3960) 234(805,3960) 234(930,4170) 234(2355,3960) 234(2480,4170) 235(805,3935) 235(930,4195) 235(2355,3935) 235(2480,4195) 236(830,3935) 236(905,4195) 236(2380,3935) 236(2455,4195) 237(855,3935) 237(880,4195) 237(2405,3935) 237(2430,4195) 238(855,4195) 238(880,3935) 238(2405,4195) 238(2430,3935) 239(830,4195) 239(905,3935) 239(2380,4195) 239(2455,3935) 240(805,4195) 240(930,3935) 240(2355,4195) 240(2480,3935) 241(780,4195) 241(955,3935) 241(2330,4195) 241(2505,3935) 242(780,4170) 242(955,3960) 242(2330,4170) 242(2505,3960) 243(780,3960) 243(955,4170) 243(2330,3960) 243(2505,4170) 244(780,3935) 244(955,4195) 244(2330,3935) 244(2505,4195) 245(780,3910) 245(955,4220) 245(2330,3910) 245(2505,4220) 246(805,3910) 246(930,4220) 246(2355,3910) 246(2480,4220) 247(830,3910) 247(905,4220) 247(2380,3910) 247(2455,4220) 248(855,3910) 248(880,4220) 248(2405,3910) 248(2430,4220) 249(855,4220) 249(880,3910) 249(2405,4220) 249(2430,3910) 250(830,4220) 250(905,3910) 250(2380,4220) 250(2455,3910) 251(805,4220) 251(930,3910) 251(2355,4220) 251(2480,3910) 252(780,4220) 252(955,3910) 252(2330,4220) 252(2505,3910)
  round 50 hole 30: 2(3275,5770) 2(3360,5075) 3(3275,5850) 3(3280,5075)
  round 30 hole 20: 4(2910,5315) 5(3030,5315) 23(3335,3645) 33(3335,3695) 34(3560,3695) 35(3560,3645) 36(3560,3545) 37(3335,3545) 38(3335,3495) 39(3560,3495) 40(3560,3285) 41(3560,3335) 42(3335,3335) 43(3335,3285) 44(3335,3185) 45(3335,3135) 46(3560,3135) 47(3560,3185) 48(3560,2925) 49(3560,2975) 50(3335,2975) 51(3335,2925) 52(3335,2825) 53(3335,2775) 54(3560,2775) 55(3560,2825) 56(3560,2565) 57(3560,2615) 58(3335,2615) 59(3335,2565) 60(3335,2465) 61(3335,2415) 62(3560,2415) 63(3560,2465) 64(3560,2205) 65(3560,2255) 66(3335,2255) 67(3335,2205) 68(3335,2105) 69(3335,2055) 70(3560,2055) 71(3560,2105) 72(3560,1845) 73(3560,1895) 74(3335,1895) 75(3335,1845) 76(3335,1745) 77(3335,1695) 78(3560,1695) 79(3560,1745) 80(3560,1485) 81(3560,1535) 82(3335,1535) 83(3335,1485) 84(3335,1385) 85(3335,1335) 86(3560,1335) 87(3560,1385) 88(3560,1125) 89(3560,1175) 90(3335,1175) 91(3335,1125) 92(3335,1025) 93(3335,975) 94(3560,975) 95(3560,1025) 96(3560,765) 97(3560,815) 98(3335,815) 99(3335,765) 100(3335,665) 101(3335,615) 102(3560,615) 103(3560,665) 104(3945,665) 105(3945,615) 106(4170,665) 107(4170,615) 108(4170,765) 109(4170,815) 110(3945,815) 111(3945,765) 112(3945,1025) 113(4170,1025) 114(4170,975) 115(3945,975) 116(3945,1125) 117(3945,1175) 118(4170,1175) 119(4170,1125) 120(4170,1335) 121(4170,1385) 122(3945,1385) 123(3945,1340) 124(3945,1485) 125(3945,1535) 126(4170,1535) 127(4170,1485) 128(4170,1695) 129(4170,1745) 130(3945,1745) 131(3945,1695) 132(3945,1845) 133(3945,1895) 134(4170,1895) 135(4170,1845) 136(4170,2105) 137(4170,2055) 138(3945,2055) 139(3945,2105) 140(3945,2205) 141(3945,2255) 142(4170,2255) 143(4170,2205) 144(4170,2415) 145(4170,2465) 146(3945,2465) 147(3945,2415) 148(3945,2565) 149(3945,2615) 150(4170,2615) 151(4170,2565) 152(4170,2825) 153(4170,2775) 154(3945,2775) 155(3945,2825) 156(4170,2925) 157(4170,2975) 158(3945,2975) 159(3945,2925) 160(3945,3135) 161(3945,3185) 162(4170,3185) 163(4170,3135) 164(4170,3285) 165(4170,3335) 166(3945,3335) 167(3945,3285) 168(3945,3495) 169(3945,3545) 170(4170,3545) 171(4170,3495) 172(4170,3645) 173(4170,3695) 174(3945,3695) 175(3945,3645) 176(700,900) 176(700,1450) 176(700,2000) 176(700,2550) 176(700,3100) 176(700,3650) 176(750,950) 176(750,1500) 176(750,2050) 176(750,2600) 176(750,3150) 176(750,3700) 176(800,900) 176(800,1450) 176(800,2000) 176(800,2550) 176(800,3100) 176(800,3650) 176(1300,900) 176(1300,1450) 176(1300,2000) 176(1300,2550) 176(1300,3100) 176(1300,3650) 176(1350,950) 176(1350,1500) 176(1350,2050) 176(1350,2600) 176(1350,3150) 176(1350,3700) 176(1400,900) 176(1400,1450) 176(1400,2000) 176(1400,2550) 176(1400,3100) 176(1400,3650) 176(2405,730) 176(2405,1090) 176(2405,1450) 176(2405,1810) 176(2405,2170) 176(2405,2530) 176(2405,2890) 176(2405,3250) 176(2405,3610) 176(2455,780) 176(2455,1140) 176(2455,1500) 176(2455,1860) 176(2455,2220) 176(2455,2580) 176(2455,2940) 176(2455,3300) 176(2455,3660) 176(2505,730) 176(2505,1090) 176(2505,1450) 176(2505,1810) 176(2505,2170) 176(2505,2530) 176(2505,2890) 176(2505,3250) 176(2505,3610) 176(2695,730) 176(2695,1090) 176(2695,1450) 176(2695,1810) 176(2695,2170) 176(2695,2530) 176(2695,2890) 176(2695,3250) 176(2695,3610) 176(2745,780) 176(2745,1140) 176(2745,1500) 176(2745,1860) 176(2745,2220) 176(2745,2580) 176(2745,2940) 176(2745,3300) 176(2745,3660) 176(2795,730) 176(2795,1090) 176(2795,1450) 176(2795,1810) 176(2795,2170) 176(2795,2530) 176(2795,2890) 176(2795,3250) 176(2795,3610) 177(700,800) 177(700,1350) 177(700,1900) 177(700,2450) 177(700,3000) 177(700,3550) 177(750,850) 177(750,1400) 177(750,1950) 177(750,2500) 177(750,3050) 177(750,3600) 177(800,800) 177(800,1350) 177(800,1900) 177(800,2450) 177(800,3000) 177(800,3550) 177(1300,800) 177(1300,1350) 177(1300,1900) 177(1300,2450) 177(1300,3000) 177(1300,3550) 177(1350,850) 177(1350,1400) 177(1350,1950) 177(1350,2500) 177(1350,3050) 177(1350,3600) 177(1400,800) 177(1400,1350) 177(1400,1900) 177(1400,2450) 177(1400,3000) 177(1400,3550) 177(2405,630) 177(2405,680) 177(2405,990) 177(2405,1040) 177(2405,1350) 177(2405,1400) 177(2405,1710) 177(2405,1760) 177(2405,2070) 177(2405,2120) 177(2405,2430) 177(2405,2480) 177(2405,2790) 177(2405,2840) 177(2405,3150) 177(2405,3200) 177(2405,3510) 177(2405,3560) 177(2455,680) 177(2455,1040) 177(2455,1400) 177(2455,1760) 177(2455,2120) 177(2455,2480) 177(2455,2840) 177(2455,3200) 177(2455,3560) 177(2505,630) 177(2505,680) 177(2505,990) 177(2505,1040) 177(2505,1350) 177(2505,1400) 177(2505,1710) 177(2505,1760) 177(2505,2070) 177(2505,2120) 177(2505,2430) 177(2505,2480) 177(2505,2790) 177(2505,2840) 177(2505,3150) 177(2505,3200) 177(2505,3510) 177(2505,3560) 177(2695,630) 177(2695,680) 177(2695,990) 177(2695,1040) 177(2695,1350) 177(2695,1400) 177(2695,1710) 177(2695,1760) 177(2695,2070) 177(2695,2120) 177(2695,2430) 177(2695,2480) 177(2695,2790) 177(2695,2840) 177(2695,3150) 177(2695,3200) 177(2695,3510) 177(2695,3560) 177(2745,680) 177(2745,1040) 177(2745,1400) 177(2745,1760) 177(2745,2120) 177(2745,2480) 177(2745,2840) 177(2745,3200) 177(2745,3560) 177(2795,630) 177(2795,680) 177(2795,990) 177(2795,1040) 177(2795,1350) 177(2795,1400) 177(2795,1710) 177(2795,1760) 177(2795,2070) 177(2795,2120) 177(2795,2430) 177(2795,2480) 177(2795,2790) 177(2795,2840) 177(2795,3150) 177(2795,3200) 177(2795,3510) 177(2795,3560) 178(700,700) 178(700,1250) 178(700,1800) 178(700,2350) 178(700,2900) 178(700,3450) 178(750,750) 178(750,1300) 178(750,1850) 178(750,2400) 178(750,2950) 178(750,3500) 178(800,700) 178(800,1250) 178(800,1800) 178(800,2350) 178(800,2900) 178(800,3450) 178(1300,700) 178(1300,1250) 178(1300,1800) 178(1300,2350) 178(1300,2900) 178(1300,3450) 178(1350,750) 178(1350,1300) 178(1350,1850) 178(1350,2400) 178(1350,2950) 178(1350,3500) 178(1400,700) 178(1400,1250) 178(1400,1800) 178(1400,2350) 178(1400,2900) 178(1400,3450) 178(2455,580) 178(2455,940) 178(2455,1300) 178(2455,1660) 178(2455,2020) 178(2455,2380) 178(2455,2740) 178(2455,3100) 178(2455,3460) 178(2745,580) 178(2745,940) 178(2745,1300) 178(2745,1660) 178(2745,2020) 178(2745,2380) 178(2745,2740) 178(2745,3100) 178(2745,3460) 179(700,600) 179(700,1150) 179(700,1700) 179(700,2250) 179(700,2800) 179(700,3350) 179(750,650) 179(750,1200) 179(750,1750) 179(750,2300) 179(750,2850) 179(750,3400) 179(800,600) 179(800,1150) 179(800,1700) 179(800,2250) 179(800,2800) 179(800,3350) 179(1300,600) 179(1300,1150) 179(1300,1700) 179(1300,2250) 179(1300,2800) 179(1300,3350) 179(1350,650) 179(1350,1200) 179(1350,1750) 179(1350,2300) 179(1350,2850) 179(1350,3400) 179(1400,600) 179(1400,1150) 179(1400,1700) 179(1400,2250) 179(1400,2800) 179(1400,3350) 214(1185,4100) 215(1220,4100) 216(1255,4099.74) 217(2735,4100) 218(2770,4100) 219(2805,4100) 220(1025,260) 221(1070,260) 222(2580,260) 223(2625,260) 224(2970,5595) 224(3290,5660) 224(3355,5660) 225(2970,5535)
  round 60 hole 30: 198(1705,5485) 198(1710,6225) 199(1710,6085) 199(1790,5485) 200(1780,6225) 200(1790,5415) 201(1705,5415) 201(1710,6155)

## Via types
v1: diameter 20, hole 10, Top Layer to Bottom Layer, 10 vias

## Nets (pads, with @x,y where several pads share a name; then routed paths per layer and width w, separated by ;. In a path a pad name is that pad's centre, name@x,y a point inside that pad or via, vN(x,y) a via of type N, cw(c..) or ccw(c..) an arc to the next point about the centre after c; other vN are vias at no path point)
BEAD_OUT: C11.1 C13.1 L2.2 L3.1
CM_IN: C3.1 C5.1 C7.1 D1.1 L1.1
CM_OUT: C8.2 C9.1 L1.4 L2.1
COMP: C20.2 R6.1 U3.3 | length 170
  Top Layer w10: U3.3@2613.9,5121.28 2652.98,5121.28 2669.47,5137.78 C20.2@2707.98,5137.78 2774.98,5137.78 R6.1@2776.48,5136.28
CS: R13.2 U3.8 | length 128.4
  Top Layer w10: R13.2@2319.47,5116.28 R13.2@2324.47,5121.28
  Top Layer w11: R13.2@2319.47,5116.28 2379.34,5116.28 2384.34,5121.28 U3.8@2438.7,5121.28
D_RED: C17.1 U2.5 | length 64
  Top Layer w11: U2.5@2494.8,4017.76 2528.74,4017.76 C17.1@2550,3996.5
D_YEL: C6.1 U1.5 | length 66.7
  Top Layer w10: U1.5@942.88,4017.95 U1.5@943.74,4018.82 977.68,4018.82 C6.1@1000,3996.5
DRV_OUT: pad.6@2665,5195 pad.6@2715,5425 R12.1 U3.5 | length 357.9
  Top Layer w11: U3.5@2613.9,5160.65 2630.65,5160.65 pad.6@2665,5195
  Top Layer w20: pad.6@2715,5425 R12.1@2715,5466.81
  Signal Layer 2 w20: pad.6@2665,5195 2715,5245 pad.6@2715,5425
FB: C20.1 C21.1 R18.1 R19.2 U3.2 | length 105.2
  Top Layer w10: U3.2@2613.9,5101.59 2664.12,5101.59 2690.93,5074.78 C20.1@2707.98,5074.78
GND: C1.2 C2.2 C6.2 C8.1 C9.2 C10.2 C11.2 C12.2 C13.2 C16.2 C17.2 C18.2 C19.2 C22.2 C23.2 C24.1 C25.2 C27.2 C28.2 C29.2 C30.2 D8.2 D23.2 D33.2 L1.3 pad.2 pad.3 pad.4 pad.5 pad.6@2080,5200 pad.6@2510,5220 pad.6@2525,5115 pad.6@2605,5220 pad.6@2710,4885 pad.102 pad.103 pad.106 pad.107 pad.198@1705,5485 pad.199@1790,5485 pad.200@1790,5415 pad.201@1705,5415 pad.220 pad.221 pad.222 pad.223 pad.226 pad.227 pad.228 pad.229 pad.230 pad.231 pad.232 pad.233 pad.234 pad.235 pad.236 pad.237 pad.238 pad.239 pad.240 pad.241 pad.242 pad.243 pad.244 pad.245 pad.246 pad.247 pad.248 pad.249 pad.250 pad.251 pad.252 R1.1 R2.1 R3.1 R4.1 R5.1 R8.1 R9.1 R15.1 R17.2 R19.1 TP2.1 TP4.1 TP6.1 U1.3 U1.9 U2.3 U2.9 U3.6 | length 7.5
  Top Layer w10: v1(868.94,4115.28) U1.9@868.94,4118.19 ; R19.1@2704.73,4931.54 R19.1@2707.98,4934.78
  other v1: 2420,4015.79 868.94,4016.85 2386.54,4065 2420,4065 2453.46,4065 835.48,4066.06 868.94,4066.06 902.41,4066.06 2420,4114.21
GNDIN: C4.2 C5.2 C7.2 D1.2 L1.2
HS: D9.3 D10.3 D11.3 D12.3 D15.3 D16.3 D17.3 D18.3 D19.3 pad.176@2405,730 pad.176@2405,1090 pad.176@2405,1450 pad.176@2405,1810 pad.176@2405,2170 pad.176@2405,2530 pad.176@2405,2890 pad.176@2405,3250 pad.176@2405,3610 pad.176@2455,780 pad.176@2455,1140 pad.176@2455,1500 pad.176@2455,1860 pad.176@2455,2220 pad.176@2455,2580 pad.176@2455,2940 pad.176@2455,3300 pad.176@2455,3660 pad.176@2505,730 pad.176@2505,1090 pad.176@2505,1450 pad.176@2505,1810 pad.176@2505,2170 pad.176@2505,2530 pad.176@2505,2890 pad.176@2505,3250 pad.176@2505,3610 pad.176@2695,730 pad.176@2695,1090 pad.176@2695,1450 pad.176@2695,1810 pad.176@2695,2170 pad.176@2695,2530 pad.176@2695,2890 pad.176@2695,3250 pad.176@2695,3610 pad.176@2745,780 pad.176@2745,1140 pad.176@2745,1500 pad.176@2745,1860 pad.176@2745,2220 pad.176@2745,2580 pad.176@2745,2940 pad.176@2745,3300 pad.176@2745,3660 pad.176@2795,730 pad.176@2795,1090 pad.176@2795,1450 pad.176@2795,1810 pad.176@2795,2170 pad.176@2795,2530 pad.176@2795,2890 pad.176@2795,3250 pad.176@2795,3610 pad.177@2405,630 pad.177@2405,680 pad.177@2405,990 pad.177@2405,1040 pad.177@2405,1350 pad.177@2405,1400 pad.177@2405,1710 pad.177@2405,1760 pad.177@2405,2070 pad.177@2405,2120 pad.177@2405,2430 pad.177@2405,2480 pad.177@2405,2790 pad.177@2405,2840 pad.177@2405,3150 pad.177@2405,3200 pad.177@2405,3510 pad.177@2405,3560 pad.177@2455,680 pad.177@2455,1040 pad.177@2455,1400 pad.177@2455,1760 pad.177@2455,2120 pad.177@2455,2480 pad.177@2455,2840 pad.177@2455,3200 pad.177@2455,3560 pad.177@2505,630 pad.177@2505,680 pad.177@2505,990 pad.177@2505,1040 pad.177@2505,1350 pad.177@2505,1400 pad.177@2505,1710 pad.177@2505,1760 pad.177@2505,2070 pad.177@2505,2120 pad.177@2505,2430 pad.177@2505,2480 pad.177@2505,2790 pad.177@2505,2840 pad.177@2505,3150 pad.177@2505,3200 pad.177@2505,3510 pad.177@2505,3560 pad.177@2695,630 pad.177@2695,680 pad.177@2695,990 pad.177@2695,1040 pad.177@2695,1350 pad.177@2695,1400 pad.177@2695,1710 pad.177@2695,1760 pad.177@2695,2070 pad.177@2695,2120 pad.177@2695,2430 pad.177@2695,2480 pad.177@2695,2790 pad.177@2695,2840 pad.177@2695,3150 pad.177@2695,3200 pad.177@2695,3510 pad.177@2695,3560 pad.177@2745,680 pad.177@2745,1040 pad.177@2745,1400 pad.177@2745,1760 pad.177@2745,2120 pad.177@2745,2480 pad.177@2745,2840 pad.177@2745,3200 pad.177@2745,3560 pad.177@2795,630 pad.177@2795,680 pad.177@2795,990 pad.177@2795,1040 pad.177@2795,1350 pad.177@2795,1400 pad.177@2795,1710 pad.177@2795,1760 pad.177@2795,2070 pad.177@2795,2120 pad.177@2795,2430 pad.177@2795,2480 pad.177@2795,2790 pad.177@2795,2840 pad.177@2795,3150 pad.177@2795,3200 pad.177@2795,3510 pad.177@2795,3560 pad.178@2455,580 pad.178@2455,940 pad.178@2455,1300 pad.178@2455,1660 pad.178@2455,2020 pad.178@2455,2380 pad.178@2455,2740 pad.178@2455,3100 pad.178@2455,3460 pad.178@2745,580 pad.178@2745,940 pad.178@2745,1300 pad.178@2745,1660 pad.178@2745,2020 pad.178@2745,2380 pad.178@2745,2740 pad.178@2745,3100 pad.178@2745,3460
NetC3_2: C3.2 C4.1 | length 88.1
  Bottom Layer w45: C4.1@321.93,5546.54 C3.2@410,5546.54
NetC15_2: C15.2 R4.2 | length 131.7
  Bottom Layer w50: R4.2@1970,5702.09 C15.2@1970,5833.74
NetC21_2: C21.2 R6.2 | length 71.1
  Top Layer w10: R6.2@2831.6,5128.41 R6.2@2839.47,5136.28
  Top Layer w35: C21.2@2839.47,5076.28 R6.2@2839.47,5136.28
NetC22_1: C22.1 U3.10 | length 64.4
  Top Layer w10: C22.1@2437.98,5017.78 2438.7,5018.5 U3.10@2438.7,5081.91
NetC25_1: C25.1 R13.1 R14.1 | length 134.3
  Top Layer w20: R14.1@2185,5123.5 R13.1@2249.26,5123.5
  Top Layer w30: R13.1@2256.48,5116.28 C25.1@2256.48,5186.28
NetC26_1: C26.1 R17.1 | length 68.9
  Top Layer w50: C26.1@2910,5805 R17.1@2978.86,5805
NetD13_1: D13.1 D14.1 pad.6@2530,4755 pad.6@2530,4930 R10.2 | length 320.8
  Top Layer w20: D13.1@2478.31,4755 pad.6@2530,4755 D14.1@2581.69,4755 ; pad.6@2530,4930 R10.2@2572.44,4930
  Signal Layer 2 w20: pad.6@2530,4755 pad.6@2530,4930
NetQ1_4: Q1.4 R12.2 | length 75.3
  Top Layer w10: Q1.4@2595,5471.73 2598.54,5468.19 ; R12.2@2654.65,5469.92 2656.38,5468.19 R12.2@2666.38,5468.19
  Top Layer w20: 2598.54,5468.19 R12.2@2656.38,5468.19
PWM_RED: pad.1@2190,4090 R3.2 TP3.1 U2.1 | length 428.5
  Top Layer w11: R3.2@2260,4088.5 2289.77,4088.5 2313.51,4112.24 U2.1@2345.2,4112.24
  Top Layer w20: pad.1@2190,4090 R3.2@2258.5,4090
  Signal Layer 2 w20: TP3.1@1925,4090 pad.1@2190,4090
PWM_YEL: pad.1@660,4090.49 R1.2 TP1.1 U1.1 | length 362.6
  Top Layer w11: R1.2@705,4088.5 733.39,4088.5 758.19,4113.31 U1.1@794.14,4113.31
  Top Layer w20: pad.1@660,4090.49 R1.2@703.01,4090.49
  Signal Layer 2 w20: TP1.1@440,4090 440.49,4090.49 pad.1@660,4090.49
RED1_1: D11.2 D12.1
RED1_2: D10.2 D11.1
RED1_3: D9.2 D10.1
RED1_4: D9.1 D19.2
RED1_5: D18.2 D19.1
RED1_6: D17.2 D18.1
RED1_7: D16.2 D17.1
RED1_8: D15.2 D16.1
RED1_9: D15.1 pad.1@2570,3785.49 pad.1@2570,4045 pad.1@2600,3785 pad.1@2600,4045 pad.1@2630,4045 pad.1@2630.49,3785.98 U2.6
RED1_SNS: D12.2 pad.1@2295,4020 pad.1@2520,405 R9.2 U2.4 | length 4365.5
  Top Layer w11: pad.1@2295,4020 2297.24,4017.76 U2.4@2345.2,4017.76
  Top Layer w20: pad.1@2520,405 R9.2@2595,405
  Signal Layer 2 w20: pad.1@2295,4020 2200,4020 2025,3845 2025,470 2090,405 pad.1@2520,405
RED2_1: D22.2 D23.4 pad.94 pad.95 pad.98 pad.99 | length 282.1
  Top Layer w28: D23.4@3420.47,766.18 3420.47,870.47 3479.53,929.53 D22.2@3479.53,1023.82
RED2_2: D21.2 D22.4 pad.86 pad.87 pad.90 pad.91 | length 282.1
  Top Layer w28: D22.4@3420.47,1126.18 3420.47,1230.47 3479.53,1289.53 D21.2@3479.53,1383.82
RED2_3: D20.2 D21.4 pad.78 pad.79 pad.82 pad.83 | length 282.1
  Top Layer w28: D21.4@3420.47,1486.18 3420.47,1590.47 3479.53,1649.53 D20.2@3479.53,1743.82
RED2_4: D20.4 D28.2 pad.70 pad.71 pad.74 pad.75 | length 282.1
  Top Layer w28: D20.4@3420.47,1846.18 3420.47,1950.47 3479.53,2009.53 D28.2@3479.53,2103.82
RED2_5: D27.2 D28.4 pad.62 pad.63 pad.66 pad.67 | length 282.1
  Top Layer w28: D28.4@3420.47,2206.18 3420.47,2310.47 3479.53,2369.53 D27.2@3479.53,2463.82
RED2_6: D26.2 D27.4 pad.54 pad.55 pad.58 pad.59 | length 282.1
  Top Layer w28: D27.4@3420.47,2566.18 3420.47,2670.47 3479.53,2729.53 D26.2@3479.53,2823.82
RED2_7: D25.2 D26.4 pad.46 pad.47 pad.50 pad.51 | length 282.1
  Top Layer w28: D26.4@3420.47,2926.18 3420.47,3030.47 3479.53,3089.53 D25.2@3479.53,3183.82
RED2_8: D24.2 D25.4 pad.36 pad.39 pad.42 pad.43 | length 282.1
  Top Layer w28: D25.4@3420.47,3286.18 3420.47,3390.47 3479.53,3449.53 D24.2@3479.53,3543.82
RED2_9: D24.4 pad.23 pad.33 R16.1 U4.3 | length 172.2
  Top Layer w20: U4.3@3197.24,3915 R16.1@3369.45,3915
RED2_BASE: Q2.1 R11.1 U4.1 | length 197.6
  Top Layer w20: U4.1@3102.76,3952.4 R11.1@3102.76,4034.25
  Top Layer w30: Q2.1@3079.45,4140.83 3079.45,4059.06 R11.1@3103.5,4035
RED2_SNS: Q2.3 R16.2 U4.2 | length 328.6
  Top Layer w20: U4.2@3102.76,3877.6 3102.76,3887.76 3260.55,4045.55 Q2.3@3260.55,4140.83
RED3_1: D32.2 D33.4 pad.110 pad.111 pad.113 pad.114 | length 282.1
  Top Layer w28: D33.4@4025.47,766.18 4025.47,870.47 4084.53,929.53 D32.2@4084.53,1023.82
RED3_2: D31.2 D32.4 pad.116 pad.117 pad.120 pad.121 | length 280
  Top Layer w28: D32.4@4025.47,1126.18 4025.47,1235.47 4079.53,1289.53 D31.2@4079.53,1383.82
